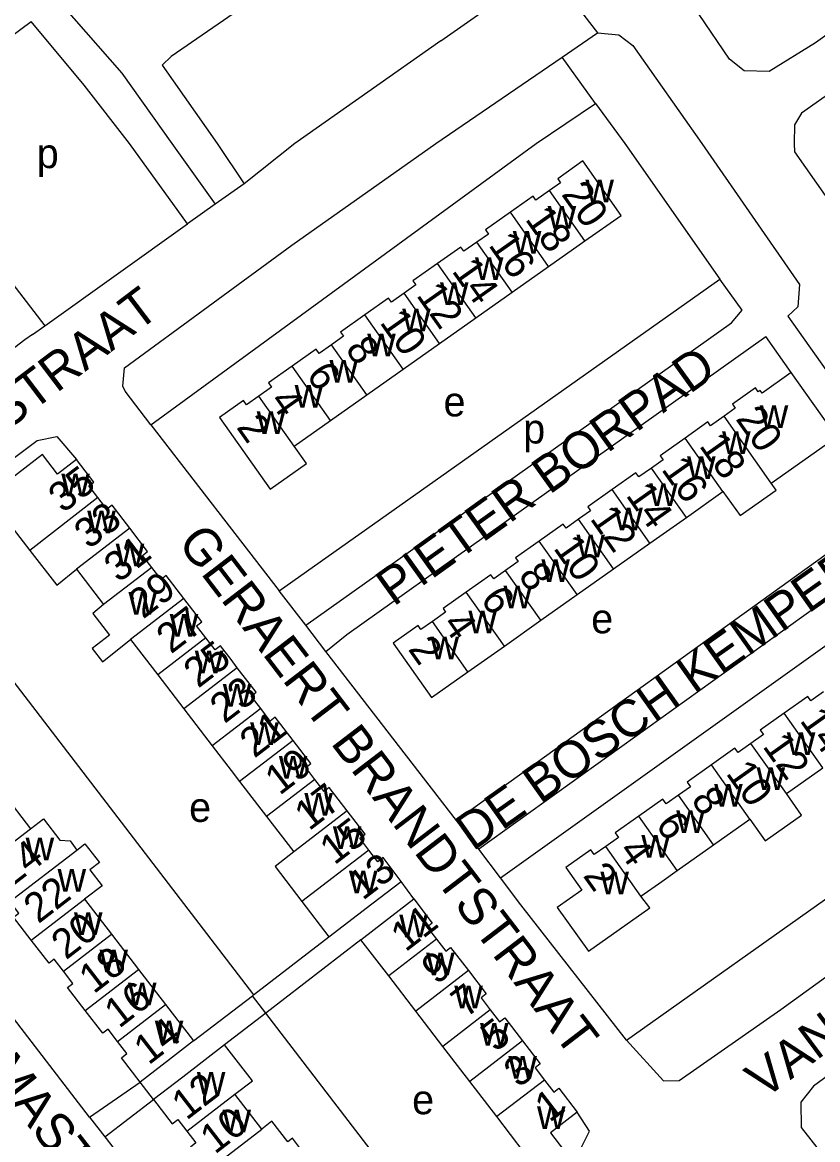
# Model space of a CAD drawing. Extents: x 158848 to 160613, y 385889 to 387762.
# Drawn here: x 159971.7 to 160079.5, y 386965 to 387116.4 of the extents above; entities that cross this region are included whole.
import ezdxf

# ---------------------------------------------------------------- set-up
doc = ezdxf.new("R2010")
doc.units = 0
for name, color, linetype in [('BLT_Basislijn', 7, 'Continuous'), ('BLT_Bebouwing', 7, 'Continuous'), ('BLT_Centroide', 7, 'Continuous'), ('BLT_Huisnummer', 7, 'Continuous'), ('BLT_Huisnummer_ tussenligend', 7, 'Continuous'), ('BLT_Onderverdeling_panden', 7, 'Continuous'), ('BLT_Straatnaam', 7, 'Continuous'), ('BLT_Vlakafsluiter', 7, 'Continuous')]:
    doc.layers.add(name, color=color, linetype=linetype)

msp = doc.modelspace()

# ---------------------------------------------------------------- linework, layer by layer
at = {"layer": 'BLT_Basislijn'}
for p, q in [((159953.88, 387102.42), (159972.89, 387116.56)), ((160049.4, 387105.44), (160044.86, 387111.72)), ((160001.76, 387094.56), (159997.86, 387091.8)), ((159962.7, 387090.95), (159974.73, 387075.31)), ((159997.86, 387091.8), (159994.08, 387089.13)), ((159974.73, 387075.31), (159994.08, 387089.13)), ((160006.51, 387039.39), (160066.23, 387081.64)), ((159973.07, 387074.13), (159974.73, 387075.31)), ((160075.46, 387076.59), (160096.68, 387046.57)), ((160075.94, 387068.97), (160072.5, 387073.85)), ((159989.1, 387061.88), (160006.51, 387039.39)), ((160089.09, 387050.38), (160030.55, 387008.25)), ((160092.78, 387046.87), (160033.56, 387004.36)), ((159955.74, 387046.28), (160003.04, 386984.63)), ((160010.13, 387034.72), (160006.51, 387039.39)), ((160012.86, 387031.17), (160010.13, 387034.72)), ((160030.55, 387008.25), (160012.86, 387031.17)), ((160053.61, 386978.5), (160111.96, 387019.88)), ((160033.56, 387004.36), (160030.55, 387008.25)), ((160036.52, 387000.48), (160033.56, 387004.36)), ((160024.75, 386997.62), (160023.04, 387000)), ((160003.04, 386984.63), (160013.26, 386992.5)), ((160017.57, 386992.1), (160004.69, 386982.16)), ((159994.9, 386978.37), (160002.88, 386984.51)), ((160002.88, 386984.51), (160003.04, 386984.63)), ((160004.69, 386982.16), (160002.88, 386984.51)), ((160004.69, 386982.16), (159999.12, 386977.87)), ((160029.66, 386949.66), (160004.69, 386982.16)), ((159980.79, 386968.05), (159987.68, 386972.8)), ((159989.49, 386970.44), (159987.68, 386972.8)), ((159982.89, 386965.37), (159989.49, 386970.44)), ((159980.79, 386968.05), (159982.89, 386965.37))]:
    msp.add_line(p, q, dxfattribs=at)
for points in [[(159916.25, 387199.14), (159932.15, 387164.56), (159934.47, 387160.07), (159942.11, 387151.9), (159962.24, 387133.95), (159973.8, 387122.55), (159985.2, 387109.53), (159991.98, 387100), (159997.86, 387091.8)], [(160112.9, 387144.8), (160108.43, 387141.31), (160109.47, 387136.09), (160109.21, 387135.2), (160079.21, 387113.67), (160072.92, 387109.76), (160069.56, 387109.86), (160067.54, 387111.42), (160063.46, 387117.49)], [(160028.44, 387113.92), (160041.97, 387123.44), (160042.68, 387124.04)], [(160006.64, 387122.02), (159991.89, 387111.82), (159990.65, 387110.63), (159998.11, 387100), (160001.76, 387094.56)], [(159994.08, 387089.13), (159986.21, 387100), (159980.09, 387107.89), (159972.89, 387116.56)], [(160044.86, 387111.72), (160049.66, 387115)], [(160049.66, 387115), (160052.56, 387114.75), (160054.47, 387113.27), (160063.8, 387100), (160077.06, 387080.91), (160076.83, 387077.86), (160075.46, 387076.59)], [(160028.44, 387113.92), (160008.63, 387100), (160001.76, 387094.56)], [(159989.1, 387061.88), (159985.65, 387066.44), (159985.33, 387067.14), (159985.56, 387069.62), (160008.23, 387086.23), (160027.75, 387100), (160044.86, 387111.72)], [(160087.53, 387111.32), (160086.79, 387110.81), (160077.3, 387104.11), (160076.35, 387102.52), (160076.31, 387100), (160076.37, 387098.89), (160118.05, 387039.54), (160120.49, 387036.53), (160122.8, 387035.89), (160124.7, 387036.28), (160127.31, 387037.47), (160134.78, 387042.54), (160135.76, 387043.25)], [(159989.1, 387061.88), (160041.34, 387100), (160049.4, 387105.44)], [(160049.4, 387105.44), (160053.38, 387100), (160066.23, 387081.64)], [(160010.13, 387034.72), (160067.85, 387075.71), (160069.27, 387077.41), (160066.23, 387081.64)], [(159973.07, 387074.13), (159972.02, 387073.38), (159970.69, 387072.37)], [(160012.86, 387031.17), (160015.69, 387033.46), (160072.5, 387073.85)], [(159955.74, 387046.28), (159973.72, 387059.77), (159976.37, 387060.31), (159979.04, 387057.18)], [(159980.79, 386968.05), (159942.54, 387017.82), (159935.06, 387027.05), (159935.38, 387030.01), (159937.2, 387031.92), (159955.74, 387046.28)], [(160036.52, 387000.48), (160095.68, 387042.71)], [(160053.61, 386978.5), (160058.61, 386972.96), (160060.74, 386973.02), (160074.51, 386982.64), (160116.71, 387013.17)], [(160053.61, 386978.5), (160039.29, 386996.84), (160036.52, 387000.48)], [(160101.95, 386989.1), (160078.94, 386972.26), (160077.25, 386970.06), (160077.28, 386966.66), (160115.04, 386918.44), (160115.49, 386917.88)], [(160029.66, 386949.66), (160046.1, 386962.05), (160047.12, 386963.25), (160048.59, 386966.15), (160046.93, 386968.73)], [(159982.89, 386965.37), (159983.05, 386965.17), (159996.82, 386947.26), (160007.03, 386934.78), (160009.52, 386934.38), (160011.47, 386935.29), (160029.66, 386949.66)]]:
    msp.add_lwpolyline(points, dxfattribs=at)
at = {"layer": 'BLT_Bebouwing'}
for p, q in [((160043.04, 387083.33), (160047.97, 387086.8)), ((160038.11, 387079.85), (160043.04, 387083.33)), ((160033.18, 387076.38), (160038.11, 387079.85)), ((160028.25, 387072.9), (160033.18, 387076.38)), ((160023.32, 387069.42), (160028.25, 387072.9)), ((160018.39, 387065.95), (160023.32, 387069.42)), ((160013.46, 387062.47), (160018.39, 387065.95)), ((160008.53, 387059), (160013.46, 387062.47)), ((160061.71, 387049.34), (160066.64, 387052.83)), ((160056.77, 387045.85), (160061.71, 387049.34)), ((160051.84, 387042.36), (160056.77, 387045.85)), ((159979.05, 387042.3), (159982.72, 387037.53)), ((160046.9, 387038.88), (160051.84, 387042.36)), ((160041.97, 387035.39), (160046.9, 387038.88)), ((160037.04, 387031.9), (160041.97, 387035.39)), ((159986.38, 387032.77), (159990.05, 387027.99)), ((160032.1, 387028.41), (160037.04, 387031.9)), ((160000.84, 387028.96), (160000, 387030.06)), ((159990.05, 387027.99), (159993.59, 387023.39)), ((159993.59, 387023.39), (159997.45, 387018.37)), ((159997.45, 387018.37), (160000, 387015.05)), ((160000, 387015.05), (160001.16, 387013.54)), ((160075.27, 387011.9), (160080.2, 387015.38)), ((160001.16, 387013.54), (160004.82, 387008.78)), ((159969.15, 387011.89), (159972.8, 387007.12)), ((160004.82, 387008.78), (160008.5, 387003.99)), ((160065.4, 387004.95), (160070.33, 387008.42)), ((160060.47, 387001.47), (160065.4, 387004.95)), ((160058.38, 387000), (160060.47, 387001.47)), ((160055.53, 386998), (160058.38, 387000)), ((159980.15, 386997.59), (159983.78, 386992.83)), ((159983.78, 386992.83), (159987.44, 386988.07)), ((160021.36, 386987.18), (160017.57, 386992.1)), ((159987.44, 386988.07), (159991.1, 386983.32)), ((160025.02, 386982.41), (160021.36, 386987.18)), ((159991.1, 386983.32), (159994.9, 386978.37)), ((160028.69, 386977.64), (160025.02, 386982.41)), ((160002.88, 386972.99), (159999.12, 386977.87)), ((160032.35, 386972.88), (160028.69, 386977.64)), ((160000.5, 386971.15), (160002.88, 386972.99)), ((160036.02, 386968.12), (160032.35, 386972.88)), ((160004.15, 386966.42), (160000.5, 386971.15))]:
    msp.add_line(p, q, dxfattribs=at)
for points in [[(160047.97, 387086.8), (160052.89, 387090.27), (160047.7, 387097.64), (160044.28, 387095.23), (160044.67, 387094.68), (160043.16, 387093.62)], [(160043.16, 387093.62), (160041.31, 387092.32), (160040.93, 387092.85), (160037.86, 387090.68)], [(160037.86, 387090.68), (160034.48, 387088.3), (160034.87, 387087.74), (160033.32, 387086.65)], [(160033.32, 387086.65), (160031.55, 387085.4), (160031.16, 387085.96), (160027.99, 387083.73)], [(160027.99, 387083.73), (160024.65, 387081.38), (160025.03, 387080.84), (160023.44, 387079.72)], [(160023.44, 387079.72), (160021.73, 387078.51), (160021.35, 387079.05), (160018.13, 387076.78)], [(160018.13, 387076.78), (160014.82, 387074.45), (160015.22, 387073.89), (160013.6, 387072.74)], [(160013.6, 387072.74), (160011.92, 387071.56), (160011.52, 387072.12), (160008.28, 387069.83)], [(160008.28, 387069.83), (160005.06, 387067.56), (160005.47, 387066.97), (160003.76, 387065.76)], [(160075.94, 387068.97), (160071.99, 387066.18), (160071.73, 387066.55), (160071.46, 387066.36), (160071.1, 387066.87), (160067.97, 387064.66), (160068.35, 387064.12), (160066.82, 387063.04)], [(160082.11, 387060.25), (160075.94, 387068.97)], [(160003.76, 387065.76), (160002.11, 387064.59), (160001.68, 387065.19), (159998.41, 387062.89)], [(159998.41, 387062.89), (160005.28, 387053.14), (160010.24, 387056.62), (160008.53, 387059)], [(160066.82, 387063.04), (160065, 387061.76), (160064.64, 387062.27), (160061.53, 387060.07)], [(160073.23, 387053.97), (160082.11, 387060.25)], [(160061.53, 387060.07), (160058.17, 387057.69), (160058.57, 387057.13), (160056.99, 387056.02)], [(159979.04, 387057.18), (159976.47, 387055.2), (159974.43, 387057.85), (159967.6, 387052.61), (159969.48, 387050.15), (159968.95, 387049.73), (159972.74, 387044.83)], [(159981.94, 387052.02), (159980.73, 387053.59), (159981.4, 387054.11), (159979.04, 387057.18)], [(160056.99, 387056.02), (160055.28, 387054.81), (160054.87, 387055.39), (160051.64, 387053.11)], [(160051.64, 387053.11), (160048.34, 387050.78), (160048.72, 387050.24), (160047.09, 387049.08)], [(160066.64, 387052.83), (160068.99, 387049.59), (160073.9, 387053.02), (160073.23, 387053.97)], [(159986.28, 387047.86), (159983.87, 387051), (159983.15, 387050.45), (159981.94, 387052.02)], [(160047.09, 387049.08), (160045.4, 387047.89), (160045.03, 387048.42), (160041.78, 387046.12)], [(159989.26, 387042.56), (159988.01, 387044.19), (159988.69, 387044.72), (159986.28, 387047.86)], [(160041.78, 387046.12), (160038.57, 387043.85), (160038.93, 387043.34), (160037.21, 387042.13)], [(159972.74, 387044.83), (159976.37, 387040.14), (159979.05, 387042.3)], [(159993.61, 387038.32), (159991.2, 387041.46), (159990.51, 387040.93), (159989.26, 387042.56)], [(160037.21, 387042.13), (160035.6, 387040.99), (160035.21, 387041.54), (160031.88, 387039.19)], [(160031.88, 387039.19), (160028.75, 387036.98), (160029.08, 387036.51), (160027.28, 387035.24)], [(159982.72, 387037.53), (159981.26, 387036.33), (159983.53, 387033.37), (159981.17, 387031.55), (159982.56, 387029.74), (159986.38, 387032.77)], [(159996.58, 387033.01), (159995.32, 387034.65), (159996.02, 387035.18), (159993.61, 387038.32)], [(160027.28, 387035.24), (160025.72, 387034.14), (160025.35, 387034.66), (160021.97, 387032.27), (160027.17, 387024.93), (160032.1, 387028.41)], [(160000, 387030.06), (159998.56, 387031.94), (159997.84, 387031.38), (159996.58, 387033.01)], [(160004.01, 387023.41), (160002.7, 387025.1), (160003.4, 387025.64), (160000.84, 387028.96)], [(160080.32, 387025.68), (160078.6, 387024.47), (160078.17, 387025.07), (160074.96, 387022.81)], [(160008.4, 387019.1), (160005.99, 387022.24), (160005.31, 387021.72), (160004.01, 387023.41)], [(160074.96, 387022.81), (160071.71, 387020.51), (160072.15, 387019.9), (160070.47, 387018.71)], [(160011.36, 387013.8), (160010.11, 387015.42), (160010.82, 387015.96), (160008.4, 387019.1)], [(160070.47, 387018.71), (160068.72, 387017.47), (160068.3, 387018.05), (160065.13, 387015.81)], [(160065.13, 387015.81), (160061.81, 387013.46), (160062.26, 387012.82), (160060.65, 387011.68)], [(160015.74, 387009.55), (160013.31, 387012.72), (160012.6, 387012.18), (160011.36, 387013.8)], [(160070.33, 387008.42), (160072.41, 387005.48), (160077.34, 387008.96), (160075.27, 387011.9)], [(160060.65, 387011.68), (160058.97, 387010.5), (160058.53, 387011.13), (160055.28, 387008.84)], [(160018.68, 387004.25), (160017.46, 387005.84), (160018.18, 387006.38), (160015.74, 387009.55)], [(160055.28, 387008.84), (160052.07, 387006.57), (160052.5, 387005.96), (160050.78, 387004.74)], [(159972.8, 387007.12), (159974.55, 387008.46), (159976.79, 387005.59), (159978.17, 387005.48), (159979.1, 387004.25)], [(159979.1, 387004.25), (159980.19, 387005.09), (159982.14, 387002.55), (159980.86, 387001.57), (159982.52, 386999.41), (159980.15, 386997.59)], [(160023.04, 387000), (160020.62, 387003.22), (160019.9, 387002.67), (160018.68, 387004.25)], [(160050.78, 387004.74), (160049.21, 387003.63), (160048.76, 387004.26), (160045.37, 387001.87)], [(160008.5, 387003.99), (160005.96, 387002.04), (160009.59, 386997.29)], [(160045.37, 387001.87), (160047.54, 386998.83)], [(160013.26, 386992.5), (160019.07, 386996.96), (160023.04, 387000)], [(160047.54, 386998.83), (160044.21, 386996.48), (160048.43, 386990.55), (160056.75, 386996.42), (160055.53, 386998)], [(159972.92, 386992.05), (159970.52, 386995.17), (159971.21, 386995.71), (159970, 386997.28)], [(160009.59, 386997.29), (160013.26, 386992.5)], [(160017.57, 386992.1), (160020.78, 386994.58), (160024.75, 386997.62)], [(160024.75, 386997.62), (160027.27, 386994.34), (160026.58, 386993.81), (160027.84, 386992.17)], [(159977.29, 386987.83), (159976.02, 386989.47), (159975.33, 386988.93), (159972.92, 386992.05)], [(160027.84, 386992.17), (160029.11, 386990.53), (160029.76, 386991.04), (160032.17, 386987.91)], [(159980.23, 386982.52), (159977.83, 386985.63), (159978.56, 386986.18), (159977.29, 386987.83)], [(160032.17, 386987.91), (160034.58, 386984.78), (160033.88, 386984.24), (160035.14, 386982.61)], [(159984.61, 386978.32), (159983.35, 386979.96), (159982.63, 386979.41), (159980.23, 386982.52)], [(160035.14, 386982.61), (160036.4, 386980.97), (160037.11, 386981.51), (160039.51, 386978.38)], [(159987.68, 386972.8), (159985.14, 386976.11), (159985.88, 386976.67), (159984.61, 386978.32)], [(159994.9, 386978.37), (159991.65, 386975.86), (159987.68, 386972.8)], [(159999.12, 386977.87), (159993.45, 386973.49), (159989.49, 386970.44)], [(160039.51, 386978.38), (160041.91, 386975.26), (160041.21, 386974.72), (160042.47, 386973.08)], [(160042.47, 386973.08), (160043.73, 386971.44), (160044.43, 386971.98), (160046.93, 386968.73)], [(159989.49, 386970.44), (159992.02, 386967.14), (159992.76, 386967.71), (159993.98, 386966.13)], [(160046.93, 386968.73), (160043.28, 386965.92), (160045.21, 386963.42), (160038.84, 386958.52), (160036.87, 386961.08), (160039.74, 386963.28), (160036.02, 386968.12)], [(160007.83, 386961.65), (160009.83, 386963.23), (160008.31, 386965.2), (160007.68, 386964.71), (160005.53, 386967.49), (160004.15, 386966.42)], [(159993.98, 386966.13), (159995.2, 386964.55), (159994.48, 386963.99), (159996.91, 386960.84)]]:
    msp.add_lwpolyline(points, dxfattribs=at)
at = {"layer": 'BLT_Onderverdeling_panden'}
for p, q in [((160047.97, 387086.8), (160043.16, 387093.62)), ((160043.04, 387083.33), (160037.86, 387090.68)), ((160038.11, 387079.85), (160033.32, 387086.65)), ((160033.18, 387076.38), (160027.99, 387083.73)), ((160028.25, 387072.9), (160023.44, 387079.72)), ((160023.32, 387069.42), (160018.13, 387076.78)), ((160018.39, 387065.95), (160013.6, 387072.74)), ((160013.46, 387062.47), (160008.28, 387069.83)), ((160008.53, 387059), (160003.76, 387065.76)), ((160073.23, 387053.97), (160066.82, 387063.04)), ((160066.64, 387052.83), (160061.53, 387060.07)), ((160061.71, 387049.34), (160056.99, 387056.02)), ((160056.77, 387045.85), (160051.64, 387053.11)), ((159981.94, 387052.02), (159972.74, 387044.83)), ((160051.84, 387042.36), (160047.09, 387049.08)), ((159986.28, 387047.86), (159979.05, 387042.3)), ((160046.9, 387038.88), (160041.78, 387046.12)), ((159989.26, 387042.56), (159982.72, 387037.53)), ((160041.97, 387035.39), (160037.21, 387042.13)), ((160037.04, 387031.9), (160031.88, 387039.19)), ((159993.61, 387038.32), (159986.38, 387032.77)), ((160032.1, 387028.41), (160027.28, 387035.24)), ((159996.58, 387033.01), (159990.05, 387027.99)), ((160000.84, 387028.96), (159993.59, 387023.39)), ((160004.01, 387023.41), (159997.45, 387018.37)), ((160080.2, 387015.38), (160074.96, 387022.81)), ((160008.4, 387019.1), (160001.16, 387013.54)), ((160075.27, 387011.9), (160070.47, 387018.71)), ((160070.33, 387008.42), (160065.13, 387015.81)), ((160011.36, 387013.8), (160004.82, 387008.78)), ((160065.4, 387004.95), (160060.65, 387011.68)), ((160015.74, 387009.55), (160008.5, 387003.99)), ((160060.47, 387001.47), (160055.28, 387008.84)), ((159965.59, 387001.59), (159972.8, 387007.12)), ((159970, 386997.28), (159979.1, 387004.25)), ((160018.68, 387004.25), (160009.59, 386997.29)), ((160055.53, 386998), (160050.78, 387004.74)), ((159972.92, 386992.05), (159980.15, 386997.59)), ((159977.29, 386987.83), (159983.78, 386992.83)), ((160027.84, 386992.17), (160021.36, 386987.18)), ((159980.23, 386982.52), (159987.44, 386988.07)), ((160032.17, 386987.91), (160025.02, 386982.41)), ((159984.61, 386978.32), (159991.1, 386983.32)), ((160035.14, 386982.61), (160028.69, 386977.64)), ((160039.51, 386978.38), (160032.35, 386972.88)), ((160042.47, 386973.08), (160036.02, 386968.12)), ((159993.98, 386966.13), (160000.5, 386971.15)), ((159996.91, 386960.84), (160004.15, 386966.42))]:
    msp.add_line(p, q, dxfattribs=at)
at = {"layer": 'BLT_Vlakafsluiter'}
msp.add_line((160042.68, 387124.04), (160049.66, 387115), dxfattribs=at)

# ---------------------------------------------------------------- texts
at = {"layer": 'BLT_Centroide'}
for s, p in [('p', (159973.66, 387096.67)), ('w', (160048.03, 387092.02)), ('w', (160042.91, 387088.47)), ('w', (160038.19, 387085.06)), ('w', (160033.05, 387081.52)), ('w', (160028.31, 387078.11)), ('w', (160023.19, 387074.56)), ('w', (160018.45, 387071.16)), ('w', (160013.33, 387067.61)), ('w', (160008.61, 387064.2)), ('e', (160028.8, 387063.02)), ('w', (160003.47, 387060.64)), ('w', (160071.66, 387061.44)), ('p', (160039.6, 387059.35)), ('w', (160066.55, 387057.91)), ('w', (160061.81, 387054.53)), ('w', (159976.98, 387052.19)), ('w', (160056.67, 387050.89)), ('w', (159980.5, 387047.16)), ('w', (160051.94, 387047.56)), ('w', (160046.81, 387043.94)), ('w', (159984.36, 387042.69)), ('w', (160042.06, 387040.59)), ('w', (159986.09, 387036.16)), ('w', (160036.92, 387037)), ('w', (159991.68, 387033.16)), ('w', (160032.16, 387033.62)), ('e', (160048.82, 387033.62)), ('w', (160027.03, 387030.09)), ('w', (159995.08, 387028.19)), ('w', (159998.88, 387023.66)), ('w', (160002.59, 387018.47)), ('w', (160075.33, 387017.11)), ('w', (160006.47, 387013.94)), ('w', (160071.23, 387012.39)), ('w', (160009.93, 387008.91)), ('w', (160065.48, 387010.14)), ('e', (159994.31, 387008.06)), ('w', (160060.34, 387006.56)), ('w', (160013.8, 387004.38)), ('w', (159972.15, 387002.84)), ('w', (160055.62, 387003.2)), ('w', (159976.48, 386998.59)), ('w', (160015.98, 386998.38)), ('w', (160050.06, 386998.23)), ('w', (159978.7, 386992.72)), ('w', (160022.8, 386992.41)), ('w', (159982.16, 386987.69)), ('w', (160026.44, 386987.28)), ('w', (159986.02, 386983.19)), ('w', (160030.26, 386982.78)), ('w', (159989.66, 386978.06)), ('w', (160033.74, 386977.75)), ('w', (160037.59, 386973.25)), ('w', (159995.36, 386971.09)), ('e', (160024.54, 386968.44)), ('w', (160041.47, 386966.44)), ('w', (159998.84, 386966))]:
    msp.add_text(s, height=4, dxfattribs=at).set_placement(p)
at = {"layer": 'BLT_Huisnummer'}
for s, rotation, p in [('20', 305.1828, (160044.68, 387093.12)), ('14', 305.1828, (160029.83, 387082.72)), ('10', 305.1828, (160020.05, 387075.76)), ('6', 305.1828, (160010.09, 387068.61)), ('2', 305.1828, (160000.63, 387061.55)), ('20', 305.2564, (160068.3, 387062.68)), ('35', 37.4461, (159977.21, 387049.81)), ('14', 305.2564, (160053.42, 387052.32)), ('10', 305.2564, (160043.59, 387045.17)), ('29', 37.4461, (159988.07, 387035.47)), ('6', 305.2564, (160033.7, 387038.23)), ('2', 305.2564, (160023.9, 387031.47)), ('25', 37.4461, (159995.54, 387026.1)), ('21', 37.4461, (160003.15, 387016.61)), ('14', 305.4225, (160076.99, 387021.8)), ('10', 305.4225, (160066.98, 387014.64)), ('17', 37.4461, (160010.57, 387006.76)), ('6', 305.4225, (160057.43, 387007.67)), ('13', 37.4461, (160017.84, 386997.33)), ('2', 305.4225, (160047.61, 387000.77)), ('22', 37.6238, (159973.87, 386994.18)), ('11', 37.5651, (160023.64, 386990.35)), ('18', 37.6238, (159981.37, 386984.66)), ('5', 37.5648, (160035.82, 386976.77)), ('14', 37.6238, (159988.81, 386975.02)), ('12', 37.6197, (159993.94, 386967.53)), ('1', 37.5648, (160043.16, 386967.24))]:
    msp.add_text(s, height=4, rotation=rotation, dxfattribs=at).set_placement(p)
at = {"layer": 'BLT_Huisnummer_ tussenligend'}
for s, rotation, p in [('18', 305.1828, (160039.76, 387089.76)), ('16', 305.1828, (160034.8, 387086.24)), ('12', 305.1828, (160025.02, 387079.43)), ('8', 305.1828, (160015.38, 387072.13)), ('4', 305.1828, (160005.11, 387065.09)), ('18', 305.2564, (160063.36, 387059.04)), ('16', 305.2564, (160058.23, 387055.84)), ('33', 37.4461, (159980.71, 387044.92)), ('12', 305.2564, (160048.56, 387049.16)), ('31', 37.4461, (159984.75, 387040.39)), ('8', 305.2564, (160038.83, 387041.43)), ('27', 37.4461, (159991.85, 387030.74)), ('4', 305.2564, (160028.54, 387034.85)), ('23', 37.4461, (159999.11, 387021.3)), ('12', 305.4225, (160071.95, 387018.31)), ('19', 37.4461, (160006.57, 387011.57)), ('8', 305.4225, (160062.24, 387011.03)), ('15', 37.4461, (160014, 387002.13)), ('24', 37.6238, (159970.18, 386999.14)), ('4', 305.4225, (160052.41, 387004.14)), ('20', 37.6238, (159977.62, 386989.28)), ('9', 37.5648, (160027.81, 386985.9)), ('16', 37.6238, (159984.81, 386979.99)), ('7', 37.5648, (160031.81, 386981.41)), ('3', 37.5648, (160038.96, 386971.93)), ('10', 37.6197, (159997.8, 386962.93))]:
    msp.add_text(s, height=4, rotation=rotation, dxfattribs=at).set_placement(p)
at = {"layer": 'BLT_Straatnaam'}
for s, height, rotation, p in [('VERBERNESTRAAT', 5, 37.1354, (159940.21, 387038.76)), ('PIETER BORPAD', 5, 35.6657, (160022.02, 387037.18)), ('DE BOSCH KEMPERPAD', 5, 35.3034, (160032.77, 387004.02)), ('GERAERT BRANDTSTRAAT', 4.9999, 307.4124, (159992.63, 387045.89)), ('VAN METERENSTRAAT', 5, 36.625, (160072.21, 386970.38)), ('VAN AITZEMASTRAAT', 5, 307.8301, (159945.46, 387001.57))]:
    msp.add_text(s, height=height, rotation=rotation, dxfattribs=at).set_placement(p)

doc.saveas('drawing.dxf')
